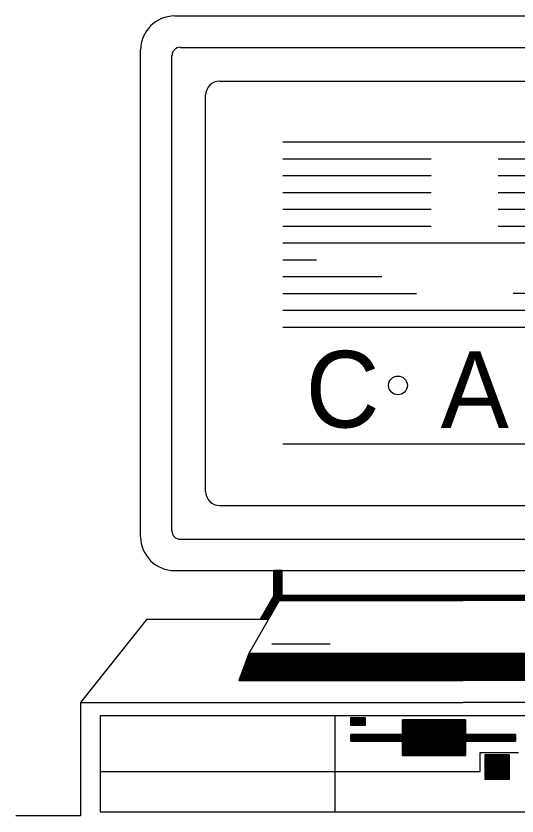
# Model space of a CAD drawing. Extents: x 18232 to 22378, y 12454 to 22381.
# Drawn here: x 22366.1067 to 22366.1879, y 22370.1457 to 22370.2752 of the extents above; entities that cross this region are included whole.
import ezdxf

# ---------------------------------------------------------------- set-up
doc = ezdxf.new("R2010")
doc.units = 0
for name, color, linetype in [('Level 1', 7, 'Continuous'), ('Level 25', 7, 'Continuous'), ('Level 50', 7, 'Continuous')]:
    doc.layers.add(name, color=color, linetype=linetype)

msp = doc.modelspace()

# ---------------------------------------------------------------- linework, layer by layer
at = {"layer": 'Level 1'}
for p, q in [((22366.14998, 22370.25479), (22366.20894, 22370.25479)), ((22366.14998, 22370.25206), (22366.17401, 22370.25206)), ((22366.1849, 22370.25206), (22366.20894, 22370.25206)), ((22366.14998, 22370.24934), (22366.17401, 22370.24934)), ((22366.1849, 22370.24934), (22366.20894, 22370.24934)), ((22366.14998, 22370.24662), (22366.17401, 22370.24662)), ((22366.1849, 22370.24662), (22366.20894, 22370.24662)), ((22366.14998, 22370.2439), (22366.17401, 22370.2439)), ((22366.1849, 22370.2439), (22366.20894, 22370.2439)), ((22366.14998, 22370.24117), (22366.17401, 22370.24117)), ((22366.1849, 22370.24117), (22366.20894, 22370.24117)), ((22366.14998, 22370.23844), (22366.20894, 22370.23844)), ((22366.14998, 22370.23573), (22366.15543, 22370.23573)), ((22366.14998, 22370.233), (22366.16604, 22370.233)), ((22366.14998, 22370.23028), (22366.17163, 22370.23028)), ((22366.20893, 22370.23028), (22366.18728, 22370.23028)), ((22366.14998, 22370.22755), (22366.20894, 22370.22755)), ((22366.14998, 22370.22482), (22366.20894, 22370.22482)), ((22366.14998, 22370.20592), (22366.20904, 22370.20592))]:
    msp.add_line(p, q, dxfattribs=at)
msp.add_circle((22366.16864, 22370.21538), 0.00152, dxfattribs=at)
at = {"layer": 'Level 25'}
for p, q in [((22366.12694, 22370.19089), (22366.12694, 22370.26969)), ((22366.13201, 22370.19184), (22366.13201, 22370.26874)), ((22366.13747, 22370.19821), (22366.13747, 22370.26236)), ((22366.13976, 22370.19592), (22366.21862, 22370.19592)), ((22366.13339, 22370.19047), (22366.2249, 22370.19047)), ((22366.13244, 22370.18539), (22366.22594, 22370.18539)), ((22366.14852, 22370.18134), (22366.14852, 22370.18539)), ((22366.14852, 22370.18535), (22366.14985, 22370.18535)), ((22366.14852, 22370.18527), (22366.14985, 22370.18527)), ((22366.14852, 22370.1852), (22366.14985, 22370.1852)), ((22366.14852, 22370.1851), (22366.14985, 22370.1851)), ((22366.14852, 22370.18502), (22366.14985, 22370.18502)), ((22366.14852, 22370.18494), (22366.14985, 22370.18494)), ((22366.14852, 22370.18486), (22366.14985, 22370.18486)), ((22366.14852, 22370.18478), (22366.14985, 22370.18478)), ((22366.14852, 22370.18469), (22366.14985, 22370.18469)), ((22366.14852, 22370.1846), (22366.14985, 22370.1846)), ((22366.14852, 22370.18453), (22366.14985, 22370.18453)), ((22366.14852, 22370.18445), (22366.14985, 22370.18445)), ((22366.14852, 22370.18436), (22366.14985, 22370.18436)), ((22366.14852, 22370.18428), (22366.14985, 22370.18428)), ((22366.14985, 22370.18134), (22366.14985, 22370.18539)), ((22366.14852, 22370.1842), (22366.14985, 22370.1842)), ((22366.14852, 22370.18411), (22366.14985, 22370.18411)), ((22366.14852, 22370.18403), (22366.14985, 22370.18403)), ((22366.14852, 22370.18396), (22366.14985, 22370.18396)), ((22366.14852, 22370.18386), (22366.14985, 22370.18386)), ((22366.14852, 22370.18378), (22366.14985, 22370.18378)), ((22366.14852, 22370.18371), (22366.14985, 22370.18371)), ((22366.14852, 22370.18362), (22366.14985, 22370.18362)), ((22366.14852, 22370.18354), (22366.14985, 22370.18354)), ((22366.14852, 22370.18345), (22366.14985, 22370.18345)), ((22366.14852, 22370.18337), (22366.14985, 22370.18337)), ((22366.14852, 22370.18329), (22366.14985, 22370.18329)), ((22366.14852, 22370.18321), (22366.14985, 22370.18321)), ((22366.14852, 22370.18314), (22366.14985, 22370.18314)), ((22366.14852, 22370.18304), (22366.14985, 22370.18304)), ((22366.14852, 22370.18296), (22366.14985, 22370.18296)), ((22366.14852, 22370.18287), (22366.14985, 22370.18287)), ((22366.14852, 22370.1828), (22366.14985, 22370.1828)), ((22366.14852, 22370.18272), (22366.14985, 22370.18272)), ((22366.14852, 22370.18262), (22366.14985, 22370.18262)), ((22366.14852, 22370.18254), (22366.14985, 22370.18254)), ((22366.14852, 22370.18247), (22366.14985, 22370.18247)), ((22366.14852, 22370.18239), (22366.14985, 22370.18239)), ((22366.14852, 22370.1823), (22366.14985, 22370.1823)), ((22366.14852, 22370.18222), (22366.14985, 22370.18222)), ((22366.14852, 22370.18214), (22366.14985, 22370.18214)), ((22366.14852, 22370.18205), (22366.14985, 22370.18205)), ((22366.14852, 22370.18197), (22366.14985, 22370.18197)), ((22366.14852, 22370.1819), (22366.14985, 22370.1819)), ((22366.14852, 22370.1818), (22366.14985, 22370.1818)), ((22366.14852, 22370.18172), (22366.14985, 22370.18172)), ((22366.14852, 22370.18165), (22366.14985, 22370.18165)), ((22366.14985, 22370.18134), (22366.14448, 22370.172)), ((22366.14852, 22370.18134), (22366.14633, 22370.17753)), ((22366.14799, 22370.18041), (22366.1493, 22370.18041)), ((22366.14803, 22370.18048), (22366.14936, 22370.18048)), ((22366.14808, 22370.18056), (22366.1494, 22370.18056)), ((22366.14813, 22370.18066), (22366.14944, 22370.18066)), ((22366.14817, 22370.18074), (22366.14949, 22370.18074)), ((22366.14822, 22370.18081), (22366.14954, 22370.18081)), ((22366.14827, 22370.1809), (22366.1496, 22370.1809)), ((22366.14833, 22370.18098), (22366.14964, 22370.18098)), ((22366.14837, 22370.18107), (22366.14968, 22370.18107)), ((22366.14841, 22370.18115), (22366.14973, 22370.18115)), ((22366.14846, 22370.18123), (22366.14977, 22370.18123)), ((22366.1485, 22370.18131), (22366.14983, 22370.18131)), ((22366.14852, 22370.18156), (22366.14985, 22370.18156)), ((22366.14852, 22370.18148), (22366.14985, 22370.18148)), ((22366.14852, 22370.18139), (22366.14985, 22370.18139)), ((22366.1494, 22370.18056), (22366.17919, 22370.18056)), ((22366.14941, 22370.18057), (22366.17919, 22370.18057)), ((22366.14945, 22370.18066), (22366.17919, 22370.18066)), ((22366.1495, 22370.18075), (22366.17919, 22370.18075)), ((22366.14954, 22370.18082), (22366.17919, 22370.18082)), ((22366.1496, 22370.18091), (22366.17919, 22370.18091)), ((22366.14964, 22370.18099), (22366.17919, 22370.18099)), ((22366.14968, 22370.18107), (22366.17919, 22370.18107)), ((22366.14974, 22370.18116), (22366.17919, 22370.18116)), ((22366.14978, 22370.18124), (22366.17919, 22370.18124)), ((22366.14984, 22370.18132), (22366.17919, 22370.18132)), ((22366.14985, 22370.18134), (22366.17919, 22370.18134)), ((22366.20852, 22370.18134), (22366.17919, 22370.18134)), ((22366.20854, 22370.18132), (22366.17919, 22370.18132)), ((22366.2086, 22370.18124), (22366.17919, 22370.18124)), ((22366.20864, 22370.18116), (22366.17919, 22370.18116)), ((22366.20868, 22370.18107), (22366.17919, 22370.18107)), ((22366.20873, 22370.18099), (22366.17919, 22370.18099)), ((22366.20877, 22370.18091), (22366.17919, 22370.18091)), ((22366.20883, 22370.18082), (22366.17919, 22370.18082)), ((22366.20888, 22370.18075), (22366.17919, 22370.18075)), ((22366.20893, 22370.18066), (22366.17919, 22370.18066)), ((22366.20897, 22370.18057), (22366.17919, 22370.18057)), ((22366.20898, 22370.18056), (22366.17919, 22370.18056)), ((22366.14723, 22370.17908), (22366.14855, 22370.17908)), ((22366.14728, 22370.17917), (22366.1486, 22370.17917)), ((22366.14733, 22370.17925), (22366.14864, 22370.17925)), ((22366.14737, 22370.17932), (22366.14869, 22370.17932)), ((22366.14742, 22370.17942), (22366.14873, 22370.17942)), ((22366.14746, 22370.1795), (22366.14879, 22370.1795)), ((22366.14751, 22370.17958), (22366.14883, 22370.17958)), ((22366.14755, 22370.17966), (22366.14888, 22370.17966)), ((22366.14761, 22370.17974), (22366.14893, 22370.17974)), ((22366.14766, 22370.17983), (22366.14897, 22370.17983)), ((22366.1477, 22370.17991), (22366.14902, 22370.17991)), ((22366.14775, 22370.17999), (22366.14906, 22370.17999)), ((22366.14779, 22370.18007), (22366.14911, 22370.18007)), ((22366.14784, 22370.18016), (22366.14917, 22370.18016)), ((22366.1479, 22370.18024), (22366.14921, 22370.18024)), ((22366.14793, 22370.18032), (22366.14926, 22370.18032)), ((22366.14646, 22370.17777), (22366.14779, 22370.17777)), ((22366.14652, 22370.17784), (22366.14784, 22370.17784)), ((22366.14656, 22370.17793), (22366.14789, 22370.17793)), ((22366.14662, 22370.17801), (22366.14793, 22370.17801)), ((22366.14666, 22370.17809), (22366.14798, 22370.17809)), ((22366.14671, 22370.17818), (22366.14802, 22370.17818)), ((22366.14675, 22370.17826), (22366.14806, 22370.17826)), ((22366.14679, 22370.17834), (22366.14813, 22370.17834)), ((22366.14685, 22370.17842), (22366.14817, 22370.17842)), ((22366.1469, 22370.1785), (22366.14822, 22370.1785)), ((22366.14695, 22370.17859), (22366.14826, 22370.17859)), ((22366.14699, 22370.17868), (22366.1483, 22370.17868)), ((22366.14703, 22370.17875), (22366.14836, 22370.17875)), ((22366.14709, 22370.17883), (22366.1484, 22370.17883)), ((22366.14713, 22370.17892), (22366.14845, 22370.17892)), ((22366.14718, 22370.17901), (22366.1485, 22370.17901)), ((22366.12792, 22370.17753), (22366.11721, 22370.16402)), ((22366.14638, 22370.17759), (22366.14769, 22370.17759)), ((22366.14642, 22370.17768), (22366.14774, 22370.17768)), ((22366.14818, 22370.17353), (22366.15765, 22370.17353)), ((22366.14448, 22370.172), (22366.14287, 22370.16761)), ((22366.14423, 22370.1713), (22366.17919, 22370.1713)), ((22366.14426, 22370.1714), (22366.17919, 22370.1714)), ((22366.14428, 22370.17148), (22366.17919, 22370.17148)), ((22366.14433, 22370.17156), (22366.17919, 22370.17156)), ((22366.14436, 22370.17164), (22366.17919, 22370.17164)), ((22366.14438, 22370.17172), (22366.17919, 22370.17172)), ((22366.14442, 22370.17181), (22366.17919, 22370.17181)), ((22366.14445, 22370.17189), (22366.17919, 22370.17189)), ((22366.14447, 22370.17197), (22366.17919, 22370.17197)), ((22366.2139, 22370.17197), (22366.17919, 22370.17197)), ((22366.21393, 22370.17189), (22366.17919, 22370.17189)), ((22366.21397, 22370.17181), (22366.17919, 22370.17181)), ((22366.21399, 22370.17172), (22366.17919, 22370.17172)), ((22366.21402, 22370.17164), (22366.17919, 22370.17164)), ((22366.21405, 22370.17156), (22366.17919, 22370.17156)), ((22366.21409, 22370.17148), (22366.17919, 22370.17148)), ((22366.21412, 22370.1714), (22366.17919, 22370.1714)), ((22366.21414, 22370.1713), (22366.17919, 22370.1713)), ((22366.14374, 22370.16999), (22366.17919, 22370.16999)), ((22366.14377, 22370.17007), (22366.17919, 22370.17007)), ((22366.1438, 22370.17016), (22366.17919, 22370.17016)), ((22366.14383, 22370.17024), (22366.17919, 22370.17024)), ((22366.14387, 22370.17032), (22366.17919, 22370.17032)), ((22366.1439, 22370.1704), (22366.17919, 22370.1704)), ((22366.14392, 22370.17048), (22366.17919, 22370.17048)), ((22366.14396, 22370.17057), (22366.17919, 22370.17057)), ((22366.14399, 22370.17066), (22366.17919, 22370.17066)), ((22366.14401, 22370.17073), (22366.17919, 22370.17073)), ((22366.14404, 22370.17081), (22366.17919, 22370.17081)), ((22366.14409, 22370.1709), (22366.17919, 22370.1709)), ((22366.14411, 22370.17099), (22366.17919, 22370.17099)), ((22366.14414, 22370.17106), (22366.17919, 22370.17106)), ((22366.14417, 22370.17115), (22366.17919, 22370.17115)), ((22366.1442, 22370.17123), (22366.17919, 22370.17123)), ((22366.21417, 22370.17123), (22366.17919, 22370.17123)), ((22366.21421, 22370.17115), (22366.17919, 22370.17115)), ((22366.21424, 22370.17106), (22366.17919, 22370.17106)), ((22366.21426, 22370.17099), (22366.17919, 22370.17099)), ((22366.21429, 22370.1709), (22366.17919, 22370.1709)), ((22366.21434, 22370.17081), (22366.17919, 22370.17081)), ((22366.21436, 22370.17073), (22366.17919, 22370.17073)), ((22366.21439, 22370.17066), (22366.17919, 22370.17066)), ((22366.21441, 22370.17057), (22366.17919, 22370.17057)), ((22366.21445, 22370.17048), (22366.17919, 22370.17048)), ((22366.21448, 22370.1704), (22366.17919, 22370.1704)), ((22366.21451, 22370.17032), (22366.17919, 22370.17032)), ((22366.21454, 22370.17024), (22366.17919, 22370.17024)), ((22366.21458, 22370.17016), (22366.17919, 22370.17016)), ((22366.2146, 22370.17007), (22366.17919, 22370.17007)), ((22366.21463, 22370.16999), (22366.17919, 22370.16999)), ((22366.14329, 22370.16875), (22366.17919, 22370.16875)), ((22366.14331, 22370.16883), (22366.17919, 22370.16883)), ((22366.14335, 22370.16893), (22366.17919, 22370.16893)), ((22366.14337, 22370.169), (22366.17919, 22370.169)), ((22366.14341, 22370.16908), (22366.17919, 22370.16908)), ((22366.14344, 22370.16917), (22366.17919, 22370.16917)), ((22366.14346, 22370.16924), (22366.17919, 22370.16924)), ((22366.1435, 22370.16933), (22366.17919, 22370.16933)), ((22366.14353, 22370.16942), (22366.17919, 22370.16942)), ((22366.14356, 22370.1695), (22366.17919, 22370.1695)), ((22366.14359, 22370.16957), (22366.17919, 22370.16957)), ((22366.14363, 22370.16966), (22366.17919, 22370.16966)), ((22366.14365, 22370.16975), (22366.17919, 22370.16975)), ((22366.14368, 22370.16982), (22366.17919, 22370.16982)), ((22366.14371, 22370.16991), (22366.17919, 22370.16991)), ((22366.21467, 22370.16991), (22366.17919, 22370.16991)), ((22366.21469, 22370.16982), (22366.17919, 22370.16982)), ((22366.21472, 22370.16975), (22366.17919, 22370.16975)), ((22366.21475, 22370.16966), (22366.17919, 22370.16966)), ((22366.21479, 22370.16957), (22366.17919, 22370.16957)), ((22366.21481, 22370.1695), (22366.17919, 22370.1695)), ((22366.21485, 22370.16942), (22366.17919, 22370.16942)), ((22366.21487, 22370.16933), (22366.17919, 22370.16933)), ((22366.21491, 22370.16924), (22366.17919, 22370.16924)), ((22366.21494, 22370.16917), (22366.17919, 22370.16917)), ((22366.21496, 22370.16908), (22366.17919, 22370.16908)), ((22366.215, 22370.169), (22366.17919, 22370.169)), ((22366.21503, 22370.16893), (22366.17919, 22370.16893)), ((22366.21505, 22370.16883), (22366.17919, 22370.16883)), ((22366.21509, 22370.16875), (22366.17919, 22370.16875)), ((22366.14289, 22370.16769), (22366.17919, 22370.16769)), ((22366.14291, 22370.16776), (22366.17919, 22370.16776)), ((22366.14295, 22370.16784), (22366.17919, 22370.16784)), ((22366.14298, 22370.16793), (22366.17919, 22370.16793)), ((22366.14301, 22370.16801), (22366.17919, 22370.16801)), ((22366.14304, 22370.16809), (22366.17919, 22370.16809)), ((22366.14308, 22370.16818), (22366.17919, 22370.16818)), ((22366.1431, 22370.16826), (22366.17919, 22370.16826)), ((22366.14313, 22370.16833), (22366.17919, 22370.16833)), ((22366.14317, 22370.16842), (22366.17919, 22370.16842)), ((22366.14319, 22370.16851), (22366.17919, 22370.16851)), ((22366.14322, 22370.16859), (22366.17919, 22370.16859)), ((22366.14325, 22370.16867), (22366.17919, 22370.16867)), ((22366.21513, 22370.16867), (22366.17919, 22370.16867)), ((22366.21515, 22370.16859), (22366.17919, 22370.16859)), ((22366.21518, 22370.16851), (22366.17919, 22370.16851)), ((22366.21521, 22370.16842), (22366.17919, 22370.16842)), ((22366.21524, 22370.16833), (22366.17919, 22370.16833)), ((22366.21527, 22370.16826), (22366.17919, 22370.16826)), ((22366.2153, 22370.16818), (22366.17919, 22370.16818)), ((22366.21533, 22370.16809), (22366.17919, 22370.16809)), ((22366.21537, 22370.16801), (22366.17919, 22370.16801)), ((22366.2154, 22370.16793), (22366.17919, 22370.16793)), ((22366.21542, 22370.16784), (22366.17919, 22370.16784)), ((22366.21546, 22370.16776), (22366.17919, 22370.16776)), ((22366.21549, 22370.16769), (22366.17919, 22370.16769)), ((22366.11721, 22370.16402), (22366.11721, 22370.14567)), ((22366.11721, 22370.16402), (22366.17919, 22370.16402)), ((22366.24116, 22370.16402), (22366.17919, 22370.16402)), ((22366.15844, 22370.14627), (22366.15844, 22370.16195)), ((22366.16099, 22370.16159), (22366.1633, 22370.16159)), ((22366.16099, 22370.16151), (22366.1633, 22370.16151)), ((22366.16099, 22370.16142), (22366.1633, 22370.16142)), ((22366.16099, 22370.16133), (22366.1633, 22370.16133)), ((22366.16099, 22370.16126), (22366.1633, 22370.16126)), ((22366.16099, 22370.16118), (22366.1633, 22370.16118)), ((22366.16099, 22370.16109), (22366.1633, 22370.16109)), ((22366.16099, 22370.161), (22366.1633, 22370.161)), ((22366.16099, 22370.16093), (22366.1633, 22370.16093)), ((22366.16939, 22370.1612), (22366.17956, 22370.1612)), ((22366.16939, 22370.1611), (22366.17956, 22370.1611)), ((22366.16939, 22370.16103), (22366.17956, 22370.16103)), ((22366.16939, 22370.16095), (22366.17956, 22370.16095)), ((22366.16099, 22370.16084), (22366.1633, 22370.16084)), ((22366.16099, 22370.16076), (22366.1633, 22370.16076)), ((22366.16099, 22370.16069), (22366.1633, 22370.16069)), ((22366.16099, 22370.16059), (22366.1633, 22370.16059)), ((22366.16099, 22370.16051), (22366.1633, 22370.16051)), ((22366.16099, 22370.16043), (22366.1633, 22370.16043)), ((22366.16099, 22370.16035), (22366.1633, 22370.16035)), ((22366.16939, 22370.16086), (22366.17956, 22370.16086)), ((22366.16939, 22370.16079), (22366.17956, 22370.16079)), ((22366.16939, 22370.1607), (22366.17956, 22370.1607)), ((22366.16939, 22370.16061), (22366.17956, 22370.16061)), ((22366.16939, 22370.16053), (22366.17956, 22370.16053)), ((22366.16939, 22370.16046), (22366.17956, 22370.16046)), ((22366.16939, 22370.16037), (22366.17956, 22370.16037)), ((22366.16939, 22370.16028), (22366.17956, 22370.16028)), ((22366.16939, 22370.1602), (22366.17956, 22370.1602)), ((22366.16939, 22370.16012), (22366.17956, 22370.16012)), ((22366.16939, 22370.16004), (22366.17956, 22370.16004)), ((22366.16939, 22370.15996), (22366.17956, 22370.15996)), ((22366.16939, 22370.15987), (22366.17956, 22370.15987)), ((22366.16939, 22370.15979), (22366.17956, 22370.15979)), ((22366.16939, 22370.15971), (22366.17956, 22370.15971)), ((22366.16939, 22370.15962), (22366.17956, 22370.15962)), ((22366.16102, 22370.1588), (22366.1877, 22370.1588)), ((22366.16102, 22370.15873), (22366.1877, 22370.15873)), ((22366.16102, 22370.15864), (22366.1877, 22370.15864)), ((22366.16102, 22370.15855), (22366.1877, 22370.15855)), ((22366.16102, 22370.15847), (22366.1877, 22370.15847)), ((22366.16102, 22370.1584), (22366.1877, 22370.1584)), ((22366.16939, 22370.15955), (22366.17956, 22370.15955)), ((22366.16939, 22370.15946), (22366.17956, 22370.15946)), ((22366.16939, 22370.15937), (22366.17956, 22370.15937)), ((22366.16939, 22370.1593), (22366.17956, 22370.1593)), ((22366.16939, 22370.15922), (22366.17956, 22370.15922)), ((22366.16939, 22370.15914), (22366.17956, 22370.15914)), ((22366.16939, 22370.15904), (22366.17956, 22370.15904)), ((22366.16939, 22370.15897), (22366.17956, 22370.15897)), ((22366.16939, 22370.15889), (22366.17956, 22370.15889)), ((22366.16102, 22370.15831), (22366.1877, 22370.15831)), ((22366.16102, 22370.15822), (22366.1877, 22370.15822)), ((22366.16102, 22370.15814), (22366.1877, 22370.15814)), ((22366.16102, 22370.15806), (22366.1877, 22370.15806)), ((22366.16102, 22370.15798), (22366.1877, 22370.15798)), ((22366.16102, 22370.1579), (22366.1877, 22370.1579)), ((22366.16102, 22370.15781), (22366.1877, 22370.15781)), ((22366.16939, 22370.15773), (22366.17956, 22370.15773)), ((22366.16939, 22370.15765), (22366.17956, 22370.15765)), ((22366.16939, 22370.15756), (22366.17956, 22370.15756)), ((22366.16939, 22370.15749), (22366.17956, 22370.15749)), ((22366.16939, 22370.1574), (22366.17956, 22370.1574)), ((22366.16939, 22370.15731), (22366.17956, 22370.15731)), ((22366.16939, 22370.15724), (22366.17956, 22370.15724)), ((22366.16939, 22370.15716), (22366.17956, 22370.15716)), ((22366.16939, 22370.15707), (22366.17956, 22370.15707)), ((22366.16939, 22370.15698), (22366.17956, 22370.15698)), ((22366.16939, 22370.15691), (22366.17956, 22370.15691)), ((22366.16939, 22370.15682), (22366.17956, 22370.15682)), ((22366.16939, 22370.15674), (22366.17956, 22370.15674)), ((22366.16939, 22370.15667), (22366.17956, 22370.15667)), ((22366.16939, 22370.15657), (22366.17956, 22370.15657)), ((22366.16939, 22370.15649), (22366.17956, 22370.15649)), ((22366.16939, 22370.15641), (22366.17956, 22370.15641)), ((22366.16939, 22370.15633), (22366.17956, 22370.15633)), ((22366.16939, 22370.15625), (22366.17956, 22370.15625)), ((22366.16939, 22370.15616), (22366.17956, 22370.15616)), ((22366.16939, 22370.15607), (22366.17956, 22370.15607)), ((22366.16939, 22370.156), (22366.17956, 22370.156)), ((22366.16939, 22370.15592), (22366.17956, 22370.15592)), ((22366.16939, 22370.15583), (22366.17956, 22370.15583)), ((22366.16939, 22370.15575), (22366.17956, 22370.15575)), ((22366.18198, 22370.15596), (22366.18816, 22370.15596)), ((22366.18198, 22370.15286), (22366.18198, 22370.15596)), ((22366.16939, 22370.15567), (22366.17956, 22370.15567)), ((22366.16939, 22370.15558), (22366.17956, 22370.15558)), ((22366.16939, 22370.1555), (22366.17956, 22370.1555)), ((22366.18276, 22370.15558), (22366.18665, 22370.15558)), ((22366.18276, 22370.1555), (22366.18665, 22370.1555)), ((22366.18276, 22370.15543), (22366.18665, 22370.15543)), ((22366.18276, 22370.15534), (22366.18665, 22370.15534)), ((22366.18276, 22370.15525), (22366.18665, 22370.15525)), ((22366.18276, 22370.15518), (22366.18665, 22370.15518)), ((22366.18276, 22370.15509), (22366.18665, 22370.15509)), ((22366.18276, 22370.15501), (22366.18665, 22370.15501)), ((22366.18276, 22370.15493), (22366.18665, 22370.15493)), ((22366.18276, 22370.15484), (22366.18665, 22370.15484)), ((22366.18276, 22370.15476), (22366.18665, 22370.15476)), ((22366.18276, 22370.15468), (22366.18665, 22370.15468)), ((22366.18276, 22370.1546), (22366.18665, 22370.1546)), ((22366.18276, 22370.15452), (22366.18665, 22370.15452)), ((22366.18276, 22370.15443), (22366.18665, 22370.15443)), ((22366.18276, 22370.15434), (22366.18665, 22370.15434)), ((22366.18276, 22370.15427), (22366.18665, 22370.15427)), ((22366.18276, 22370.15419), (22366.18665, 22370.15419)), ((22366.18276, 22370.1541), (22366.18665, 22370.1541)), ((22366.18276, 22370.15401), (22366.18665, 22370.15401)), ((22366.18276, 22370.15394), (22366.18665, 22370.15394)), ((22366.18276, 22370.15385), (22366.18665, 22370.15385)), ((22366.18276, 22370.15377), (22366.18665, 22370.15377)), ((22366.18276, 22370.1537), (22366.18665, 22370.1537)), ((22366.18276, 22370.1536), (22366.18665, 22370.1536)), ((22366.18276, 22370.15352), (22366.18665, 22370.15352)), ((22366.18276, 22370.15344), (22366.18665, 22370.15344)), ((22366.18276, 22370.15336), (22366.18665, 22370.15336)), ((22366.18276, 22370.15328), (22366.18665, 22370.15328)), ((22366.18276, 22370.15319), (22366.18665, 22370.15319)), ((22366.12041, 22370.15286), (22366.18198, 22370.15286)), ((22366.18276, 22370.15311), (22366.18665, 22370.15311)), ((22366.18276, 22370.15303), (22366.18665, 22370.15303)), ((22366.18276, 22370.15295), (22366.18665, 22370.15295)), ((22366.18276, 22370.15286), (22366.18665, 22370.15286)), ((22366.18276, 22370.15278), (22366.18665, 22370.15278)), ((22366.18276, 22370.1527), (22366.18665, 22370.1527)), ((22366.18276, 22370.15261), (22366.18665, 22370.15261)), ((22366.18276, 22370.15254), (22366.18665, 22370.15254)), ((22366.18276, 22370.15246), (22366.18665, 22370.15246)), ((22366.18276, 22370.15236), (22366.18665, 22370.15236)), ((22366.18276, 22370.15228), (22366.18665, 22370.15228)), ((22366.18276, 22370.15221), (22366.18665, 22370.15221)), ((22366.18276, 22370.15212), (22366.18665, 22370.15212)), ((22366.18276, 22370.15204), (22366.18665, 22370.15204)), ((22366.18276, 22370.15195), (22366.18665, 22370.15195)), ((22366.18276, 22370.15187), (22366.18665, 22370.15187)), ((22366.18276, 22370.15179), (22366.18665, 22370.15179)), ((22366.18276, 22370.15171), (22366.18665, 22370.15171)), ((22366.18276, 22370.15164), (22366.18665, 22370.15164)), ((22366.11721, 22370.14567), (22366.10674, 22370.14567))]:
    msp.add_line(p, q, dxfattribs=at)
for points in [[(22366.14852, 22370.18539), (22366.14852, 22370.18134), (22366.14633, 22370.17753), (22366.14766, 22370.17753), (22366.14985, 22370.18134), (22366.14985, 22370.18539)], [(22366.14985, 22370.18134), (22366.1494, 22370.18056), (22366.17919, 22370.18056), (22366.17919, 22370.18134)], [(22366.20852, 22370.18134), (22366.20898, 22370.18056), (22366.17919, 22370.18056), (22366.17919, 22370.18134)], [(22366.14448, 22370.172), (22366.14287, 22370.16761), (22366.17919, 22370.16761), (22366.17919, 22370.172)], [(22366.21389, 22370.172), (22366.21551, 22370.16761), (22366.17919, 22370.16761), (22366.17919, 22370.172)], [(22366.12041, 22370.16195), (22366.23816, 22370.16195), (22366.23816, 22370.14627), (22366.12041, 22370.14627)], [(22366.16099, 22370.1616), (22366.1633, 22370.1616), (22366.1633, 22370.16031), (22366.16099, 22370.16031)], [(22366.16939, 22370.16121), (22366.16939, 22370.15886), (22366.16102, 22370.15886), (22366.16102, 22370.15778), (22366.16939, 22370.15778), (22366.16939, 22370.15545), (22366.17956, 22370.15545), (22366.17956, 22370.15778), (22366.1877, 22370.15778), (22366.1877, 22370.15886), (22366.17956, 22370.15886), (22366.17956, 22370.16121)], [(22366.18276, 22370.15565), (22366.18665, 22370.15565), (22366.18665, 22370.1516), (22366.18276, 22370.1516)]]:
    msp.add_lwpolyline(points, close=True, dxfattribs=at)
for points in [[(22366.16939, 22370.15886), (22366.16939, 22370.16121), (22366.17956, 22370.16121), (22366.17956, 22370.15886)], [(22366.16939, 22370.15778), (22366.16102, 22370.15778), (22366.16102, 22370.15886), (22366.16939, 22370.15886)], [(22366.17956, 22370.15886), (22366.1877, 22370.15886), (22366.1877, 22370.15778), (22366.17956, 22370.15778)], [(22366.17956, 22370.15778), (22366.17956, 22370.15545), (22366.16939, 22370.15545), (22366.16939, 22370.15778)]]:
    msp.add_lwpolyline(points, dxfattribs=at)
for centre, start, end in [((22366.13338, 22370.26874), 90, 180), ((22366.13338, 22370.19184), 180, 270)]:
    msp.add_arc(centre, 0.00138, start, end, dxfattribs=at)
at = {"layer": 'Level 50'}
for p, q in [((22366.13244, 22370.27519), (22366.22594, 22370.27519)), ((22366.13339, 22370.27011), (22366.2249, 22370.27011)), ((22366.13976, 22370.26466), (22366.21862, 22370.26466)), ((22366.12792, 22370.17753), (22366.14766, 22370.17753)), ((22366.14448, 22370.172), (22366.17919, 22370.172)), ((22366.21389, 22370.172), (22366.17919, 22370.172)), ((22366.14287, 22370.16761), (22366.17919, 22370.16761)), ((22366.21551, 22370.16761), (22366.17919, 22370.16761))]:
    msp.add_line(p, q, dxfattribs=at)
for centre, radius, start, end in [((22366.13244, 22370.26969), 0.0055, 90, 180), ((22366.13976, 22370.26236), 0.00229, 90, 180), ((22366.13976, 22370.19821), 0.00229, 180, 270), ((22366.13244, 22370.19089), 0.0055, 180, 270)]:
    msp.add_arc(centre, radius, start, end, dxfattribs=at)

# ---------------------------------------------------------------- texts
at = {"layer": 'Level 1'}
for s, p in [('C', (22366.15368, 22370.20857)), ('A', (22366.17555, 22370.20847))]:
    msp.add_text(s, height=0.0124, dxfattribs=at).set_placement(p)

doc.saveas('drawing.dxf')
